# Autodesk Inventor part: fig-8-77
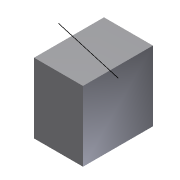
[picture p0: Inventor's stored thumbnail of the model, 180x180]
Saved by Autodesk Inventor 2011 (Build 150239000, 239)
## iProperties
Created: 2009-04
Part Number: fig-8-77
Document SubType Name: Modeling
Designer: Sham
Density: 1 g/cm^3
Author: Sham
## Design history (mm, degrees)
sketch "Sketch5"
  geometry: L1 (14, -20)-(0, -20); L2 (0, -20)-(0, 0); L3 (0, 0)-(14, 0); L4 (14, 0)-(14, -20)
  constraints: 8 end point
extrude "Extrusion2" new body sketch "Sketch5" distance "d3" = 20; taper "d4" = 0 deg
sketch "Sketch6"
  geometry: L1 (-5, 12)-(17, 7)
  constraints: 2 end point
body "Solid2"
